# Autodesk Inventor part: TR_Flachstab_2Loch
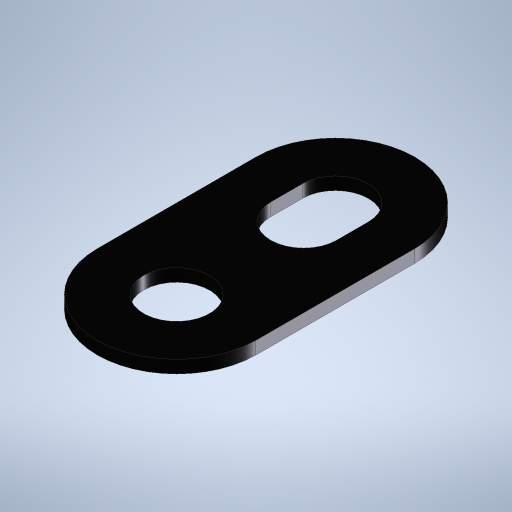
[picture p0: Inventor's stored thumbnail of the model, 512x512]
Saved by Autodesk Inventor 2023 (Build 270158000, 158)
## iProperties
Created: 2023-11
Part Number: TR_Flachstab_2Loch
Material: Edelstahl
Document SubType Name: Modeling
Designer: Admin
Density: 8 g/cm^3
Appearance: Halbpoliert
Author: Admin
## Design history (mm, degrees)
sketch "Skizze1"
  geometry: L1 (0, 5)-(0, -5); L2 (-5, 5)-(-5, -5); L3 (5, -5)-(5, 5); L4 (0, -5)-(0, -3); L5 (2.075, -5)-(2.075, -3); L6 (-2.075, -3)-(-2.075, -5); C1 r 2.075 at (0, 5); A1 r 5 centre (0, 5) between (5, 5) and (-5, 5); A2 r 5 centre (0, -5) between (-5, -5) and (5, -5); A3 r 2.075 centre (0, -5) between (-2.075, -5) and (2.075, -5); A4 r 2.075 centre (0, -3) between (2.075, -3) and (-2.075, -3); 4 further points
  constraints: 16 end point, 8 point on circle, 8 tangent, 5 centre point, 3 midpoint, 2 parallel, 1 coincident, 1 horizontal alignment, 1 point on line, 1 vertical, 1 vertical alignment
  dimensions: "d0" = 10 distance of L1.start L1.end (computed from Loch, Einheitsmaß); "d1" = 5 radius of A1 (= 0.5 x Einheitsmaß); "d2" = 4.15 diameter of C1 (= 2 x Radius); "d3" = 2 distance of L1.end L4.end; "d4" = 4.15 diameter of A4 (= 2 x Radius)
extrude "Extrusion1" new body sketch "Skizze1" distance "d5" = 0.8 (= Dicke); taper "d6" = 0 deg
node "Volumenkörper1"
other parameters: "Radius" = 2.075 [user parameter; used in 2 equation terms], "Fasen" = 0.5 [user parameter], "Dicke" = 0.8 [user parameter; used in 1 equation term]
